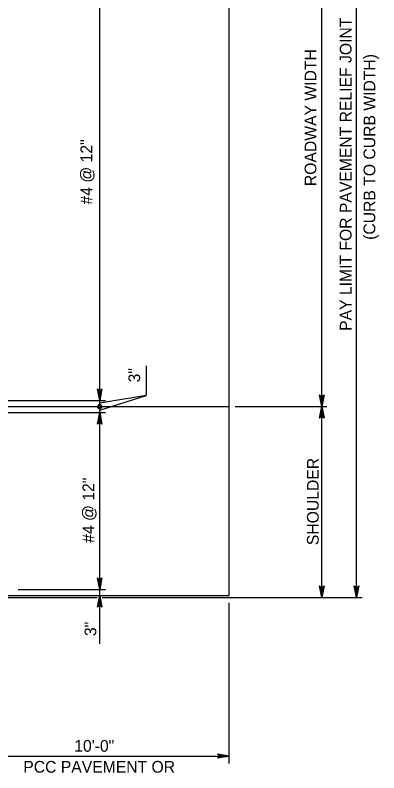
# Model space of a CAD drawing. Extents: x 2084213 to 2099800, y 976677 to 981262.
# Drawn here: x 2095105 to 2095410, y 977475 to 978110 of the extents above; entities that cross this region are included whole.
import ezdxf

# ---------------------------------------------------------------- set-up
doc = ezdxf.new("R2010")
doc.units = 0
doc.layers.add('1', color=7, linetype='Continuous')

msp = doc.modelspace()

# ---------------------------------------------------------------- linework, layer by layer
at = {"layer": '1'}
for p, q in [((2095175.84, 977583.03), (2095175.84, 978452.73)), ((2095391.19, 977621.85), (2095391.19, 978421.85)), ((2095284.34, 977623.52), (2095284.34, 978420.18)), ((2095362.09, 977781.85), (2095362.09, 978261.85)), ((2095214.75, 977816.1), (2095214.75, 977790.98)), ((2095049.27, 977786.85), (2095180.61, 977786.85)), ((2095175.84, 977778.87), (2095214.75, 977790.98)), ((2095214.75, 977790.98), (2095175.84, 977784.76)), ((2094581.64, 977781.85), (2095284.34, 977781.85)), ((2095289.36, 977781.85), (2095366.19, 977781.85)), ((2095362.09, 977621.85), (2095362.09, 977781.85)), ((2095053.37, 977776.85), (2095180.61, 977776.85)), ((2095107.36, 977628.52), (2095180.61, 977628.52)), ((2094639.27, 977623.52), (2095284.34, 977623.52)), ((2094887.5, 977621.85), (2095173.8, 977621.85)), ((2095178.02, 977621.85), (2095395.99, 977621.85)), ((2095284.34, 977482.75), (2095284.34, 977617.31)), ((2095084.34, 977488.97), (2095284.34, 977488.97))]:
    msp.add_line(p, q, dxfattribs=at)
for points in [[(2095175.84, 977786.85), (2095174, 977796.64), (2095174.26, 977796.26), (2095174.52, 977795.88), (2095174.85, 977795.69), (2095175.18, 977795.49), (2095175.51, 977795.44), (2095175.84, 977795.38), (2095176.16, 977795.44), (2095176.49, 977795.49), (2095176.82, 977795.69), (2095177.15, 977795.88), (2095177.41, 977796.26), (2095177.67, 977796.64), (2095175.84, 977786.85), (2095177.41, 977796.26), (2095177.15, 977795.88), (2095175.84, 977786.85), (2095176.82, 977795.69), (2095176.49, 977795.49), (2095175.84, 977786.85), (2095176.16, 977795.44), (2095175.84, 977795.38), (2095175.84, 977786.85), (2095175.51, 977795.44), (2095175.18, 977795.49), (2095175.84, 977786.85), (2095174.85, 977795.69), (2095174.52, 977795.88), (2095175.84, 977786.85), (2095174.26, 977796.26)], [(2095362.09, 977781.85), (2095360.26, 977791.64), (2095360.52, 977791.26), (2095360.78, 977790.88), (2095361.11, 977790.69), (2095361.44, 977790.49), (2095361.77, 977790.44), (2095362.09, 977790.38), (2095362.42, 977790.44), (2095362.75, 977790.49), (2095363.08, 977790.69), (2095363.41, 977790.88), (2095363.67, 977791.26), (2095363.93, 977791.64), (2095362.09, 977781.85), (2095363.67, 977791.26), (2095363.41, 977790.88), (2095362.09, 977781.85), (2095363.08, 977790.69), (2095362.75, 977790.49), (2095362.09, 977781.85), (2095362.42, 977790.44), (2095362.09, 977790.38), (2095362.09, 977781.85), (2095361.77, 977790.44), (2095361.44, 977790.49), (2095362.09, 977781.85), (2095361.11, 977790.69), (2095360.78, 977790.88), (2095362.09, 977781.85), (2095360.52, 977791.26)], [(2095362.09, 977781.85), (2095363.93, 977772.06), (2095363.67, 977772.44), (2095363.41, 977772.82), (2095363.08, 977773.01), (2095362.75, 977773.21), (2095362.42, 977773.26), (2095362.09, 977773.32), (2095361.77, 977773.26), (2095361.44, 977773.21), (2095361.11, 977773.01), (2095360.78, 977772.82), (2095360.52, 977772.44), (2095360.26, 977772.06), (2095362.09, 977781.85), (2095360.52, 977772.44), (2095360.78, 977772.82), (2095362.09, 977781.85), (2095361.11, 977773.01), (2095361.44, 977773.21), (2095362.09, 977781.85), (2095361.77, 977773.26), (2095362.09, 977773.32), (2095362.09, 977781.85), (2095362.42, 977773.26), (2095362.75, 977773.21), (2095362.09, 977781.85), (2095363.08, 977773.01), (2095363.41, 977772.82), (2095362.09, 977781.85), (2095363.67, 977772.44)], [(2095175.84, 977776.85), (2095177.67, 977767.06), (2095177.41, 977767.44), (2095177.15, 977767.82), (2095176.82, 977768.01), (2095176.49, 977768.21), (2095176.16, 977768.26), (2095175.84, 977768.32), (2095175.51, 977768.26), (2095175.18, 977768.21), (2095174.85, 977768.01), (2095174.52, 977767.82), (2095174.26, 977767.44), (2095174, 977767.06), (2095175.84, 977776.85), (2095174.26, 977767.44), (2095174.52, 977767.82), (2095175.84, 977776.85), (2095174.85, 977768.01), (2095175.18, 977768.21), (2095175.84, 977776.85), (2095175.51, 977768.26), (2095175.84, 977768.32), (2095175.84, 977776.85), (2095176.16, 977768.26), (2095176.49, 977768.21), (2095175.84, 977776.85), (2095176.82, 977768.01), (2095177.15, 977767.82), (2095175.84, 977776.85), (2095177.41, 977767.44)], [(2095175.84, 977628.52), (2095174, 977638.3), (2095174.26, 977637.92), (2095174.52, 977637.55), (2095174.85, 977637.35), (2095175.18, 977637.16), (2095175.51, 977637.1), (2095175.84, 977637.05), (2095176.16, 977637.1), (2095176.49, 977637.16), (2095176.82, 977637.35), (2095177.15, 977637.55), (2095177.41, 977637.92), (2095177.67, 977638.3), (2095175.84, 977628.52), (2095177.41, 977637.92), (2095177.15, 977637.55), (2095175.84, 977628.52), (2095176.82, 977637.35), (2095176.49, 977637.16), (2095175.84, 977628.52), (2095176.16, 977637.1), (2095175.84, 977637.05), (2095175.84, 977628.52), (2095175.51, 977637.1), (2095175.18, 977637.16), (2095175.84, 977628.52), (2095174.85, 977637.35), (2095174.52, 977637.55), (2095175.84, 977628.52), (2095174.26, 977637.92)], [(2095362.09, 977621.85), (2095360.26, 977631.64), (2095360.52, 977631.26), (2095360.78, 977630.88), (2095361.11, 977630.69), (2095361.44, 977630.49), (2095361.77, 977630.44), (2095362.09, 977630.38), (2095362.42, 977630.44), (2095362.75, 977630.49), (2095363.08, 977630.69), (2095363.41, 977630.88), (2095363.67, 977631.26), (2095363.93, 977631.64), (2095362.09, 977621.85), (2095363.67, 977631.26), (2095363.41, 977630.88), (2095362.09, 977621.85), (2095363.08, 977630.69), (2095362.75, 977630.49), (2095362.09, 977621.85), (2095362.42, 977630.44), (2095362.09, 977630.38), (2095362.09, 977621.85), (2095361.77, 977630.44), (2095361.44, 977630.49), (2095362.09, 977621.85), (2095361.11, 977630.69), (2095360.78, 977630.88), (2095362.09, 977621.85), (2095360.52, 977631.26)], [(2095391.19, 977621.85), (2095389.35, 977631.64), (2095389.61, 977631.26), (2095389.88, 977630.88), (2095390.2, 977630.69), (2095390.53, 977630.49), (2095390.86, 977630.44), (2095391.19, 977630.38), (2095391.52, 977630.44), (2095391.84, 977630.49), (2095392.17, 977630.69), (2095392.5, 977630.88), (2095392.76, 977631.26), (2095393.02, 977631.64), (2095391.19, 977621.85), (2095392.76, 977631.26), (2095392.5, 977630.88), (2095391.19, 977621.85), (2095392.17, 977630.69), (2095391.84, 977630.49), (2095391.19, 977621.85), (2095391.52, 977630.44), (2095391.19, 977630.38), (2095391.19, 977621.85), (2095390.86, 977630.44), (2095390.53, 977630.49), (2095391.19, 977621.85), (2095390.2, 977630.69), (2095389.88, 977630.88), (2095391.19, 977621.85), (2095389.61, 977631.26)], [(2095175.84, 977623.52), (2095177.67, 977613.73), (2095177.41, 977614.11), (2095177.15, 977614.48), (2095176.82, 977614.68), (2095176.49, 977614.87), (2095176.16, 977614.93), (2095175.84, 977614.99), (2095175.51, 977614.93), (2095175.18, 977614.87), (2095174.85, 977614.68), (2095174.52, 977614.48), (2095174.26, 977614.11), (2095174, 977613.73), (2095175.84, 977623.52), (2095174.26, 977614.11), (2095174.52, 977614.48), (2095175.84, 977623.52), (2095174.85, 977614.68), (2095175.18, 977614.87), (2095175.84, 977623.52), (2095175.51, 977614.93), (2095175.84, 977614.99), (2095175.84, 977623.52), (2095176.16, 977614.93), (2095176.49, 977614.87), (2095175.84, 977623.52), (2095176.82, 977614.68), (2095177.15, 977614.48), (2095175.84, 977623.52), (2095177.41, 977614.11)], [(2095284.34, 977488.97), (2095274.55, 977487.13), (2095274.93, 977487.39), (2095275.3, 977487.66), (2095275.5, 977487.98), (2095275.69, 977488.31), (2095275.75, 977488.64), (2095275.81, 977488.97), (2095275.75, 977489.3), (2095275.69, 977489.62), (2095275.5, 977489.95), (2095275.3, 977490.28), (2095274.93, 977490.54), (2095274.55, 977490.8), (2095284.34, 977488.97), (2095274.93, 977490.54), (2095275.3, 977490.28), (2095284.34, 977488.97), (2095275.5, 977489.95), (2095275.69, 977489.62), (2095284.34, 977488.97), (2095275.75, 977489.3), (2095275.81, 977488.97), (2095284.34, 977488.97), (2095275.75, 977488.64), (2095275.69, 977488.31), (2095284.34, 977488.97), (2095275.5, 977487.98), (2095275.3, 977487.66), (2095284.34, 977488.97), (2095274.93, 977487.39)]]:
    msp.add_lwpolyline(points, dxfattribs=at)
for radius in [1.75, 0.875]:
    msp.add_circle((2095175.84, 977781.85), radius, dxfattribs=at)

# ---------------------------------------------------------------- texts
for s, height, p in [('PAY LIMIT FOR PAVEMENT RELIEF JOINT', 9.8425, (2095387.04, 977845.24)), ('ROADWAY WIDTH', 9.8425, (2095357.54, 977966.57)), ('(CURB TO CURB WIDTH)', 9.8425, (2095406.96, 977921.54)), ('#4 @ 12"', 9.843, (2095169.56, 977951.16)), ('3"', 9.843, (2095209.75, 977802.08)), ('SHOULDER', 9.843, (2095359.48, 977665.69)), ('#4 @ 12"', 9.843, (2095171.28, 977667.64)), ('3"', 9.843, (2095173.02, 977589.48))]:
    msp.add_text(s, height=height, rotation=90, dxfattribs=at).set_placement(p)
for s, height, p in [('10\'-0"', 9.843, (2095154.51, 977492.56)), ('PCC PAVEMENT OR', 9.8425, (2095111.79, 977475))]:
    msp.add_text(s, height=height, dxfattribs=at).set_placement(p)

doc.saveas('drawing.dxf')
